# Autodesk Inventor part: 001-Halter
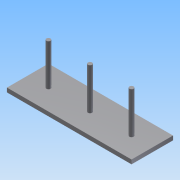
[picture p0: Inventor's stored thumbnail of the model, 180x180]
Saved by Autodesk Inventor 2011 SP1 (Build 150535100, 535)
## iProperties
Created: 2010-12
Part Number: 001-Halter
Document SubType Name: Modeling
Designer: Udo.Huebner
Density: 1 g/cm^3
Author: Udo.Huebner
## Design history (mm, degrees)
sketch "Skizze1"
  geometry: L1 (-150, 50)-(150, 50); L2 (150, 50)-(150, -50); L3 (150, -50)-(-150, -50); L4 (-150, -50)-(-150, 50); 3 further points
  constraints: 8 end point, 2 midpoint, 2 parallel, 1 horizontal, 1 horizontal alignment, 1 perpendicular, 1 vertical alignment
  dimensions: "d0" = 300 distance of L2.end L3.end; "d1" = 100 distance of L1.end L2.end
extrude "Extrusion1" new body sketch "Skizze1" distance "d2" = 10; taper "d3" = 0 deg
sketch "Skizze2"
  geometry: C1 r 5 at (0, 0); 1 further point
  constraints: 1 centre point, 1 coincident
  dimensions: "d4" = 10 diameter of C1
extrude "Extrusion2" join sketch "Skizze2" distance "d5" = 100; taper "d6" = 0 deg
pattern_linear "Rechteckige Anordnung1" dims "d9" = 100
node "Volumenkörper1"
